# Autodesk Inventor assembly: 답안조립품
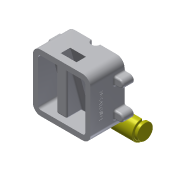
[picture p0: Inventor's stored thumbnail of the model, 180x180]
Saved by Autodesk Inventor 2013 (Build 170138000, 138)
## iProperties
Created: 2018-01
Part Number: 답안조립품
Document SubType Name: Assembly
Designer: Administrator
Author: Administrator
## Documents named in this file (3)
- C:\Users\Administrator\Desktop\480107V1028\답안조립품.iam
- C:\Users\Administrator\Desktop\480107V1028\본체.ipt
- C:\Users\Administrator\Desktop\480107V1028\핸들축.ipt
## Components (1 placed, 1 different names)
1. 핸들축:1
